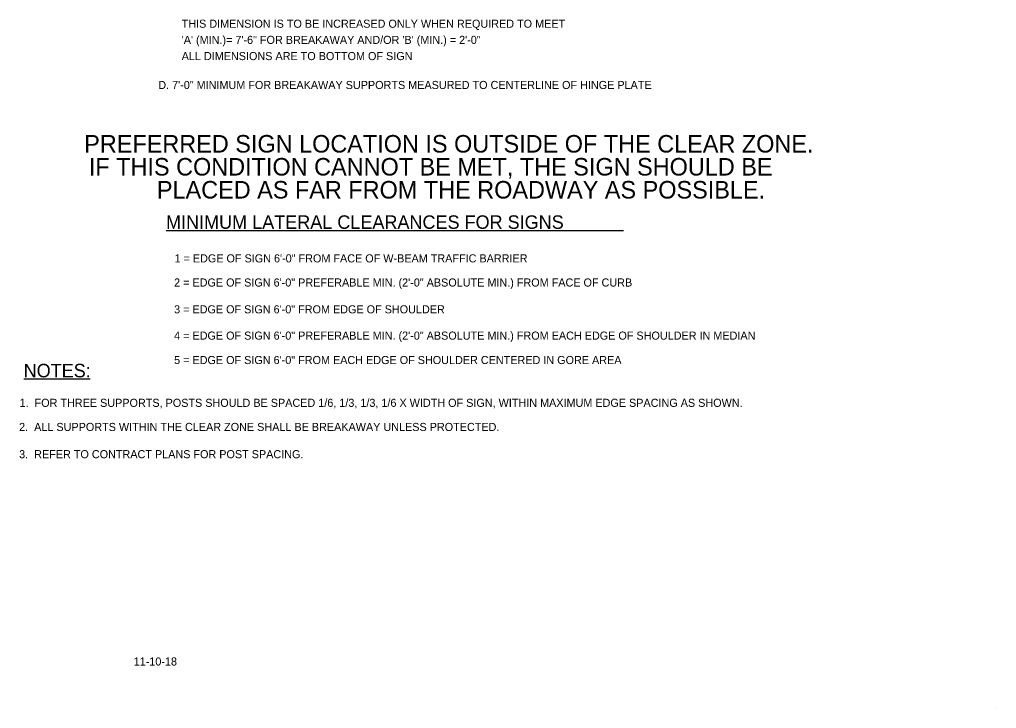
# Model space of a CAD drawing. Extents: x 139.2 to 146.5, y 202.4 to 212.6.
# Drawn here: x 139.25 to 146.5, y 202.38 to 207.49 of the extents above; entities that cross this region are included whole.
import ezdxf

# ---------------------------------------------------------------- set-up
doc = ezdxf.new("R2010")
doc.units = 0
for name, color, linetype in [('DETL-LINE', 7, 'Continuous'), ('DETL-NOTE', 7, 'Continuous'), ('TTLB-TEXT', 7, 'Continuous')]:
    doc.layers.add(name, color=color, linetype=linetype)

msp = doc.modelspace()

# ---------------------------------------------------------------- linework, layer by layer
at = {"layer": 'DETL-LINE'}
msp.add_line((140.3404, 205.922), (143.7331, 205.922), dxfattribs=at)
at = {"layer": 'DETL-NOTE'}
msp.add_line((139.2842, 204.8205), (139.7782, 204.8205), dxfattribs=at)
at = {"layer": 'TTLB-TEXT'}
msp.add_line((146.4995, 202.3768), (146.4995, 202.3768), dxfattribs=at)

# ---------------------------------------------------------------- texts
at = {"layer": 'DETL-LINE'}
msp.add_text('MINIMUM LATERAL CLEARANCES FOR SIGNS', height=0.100002, dxfattribs=at).set_placement((140.34, 205.9342))
at = {"layer": 'DETL-NOTE'}
for s, height, p in [('THIS DIMENSION IS TO BE INCREASED ONLY WHEN REQUIRED TO MEET ', 0.06, (140.4561, 207.4257)), ('\'A\' (MIN.)= 7\'-6" FOR BREAKAWAY AND/OR \'B\' (MIN.) = 2\'-0" ', 0.06, (140.4561, 207.3057)), ('ALL DIMENSIONS ARE TO BOTTOM OF SIGN', 0.06, (140.4561, 207.1857)), ('D. 7\'-0" MINIMUM FOR BREAKAWAY SUPPORTS MEASURED TO CENTERLINE OF HINGE PLATE', 0.06, (140.2826, 206.9712)), ('PREFERRED SIGN LOCATION IS OUTSIDE OF THE CLEAR ZONE.', 0.13, (139.7333, 206.5)), ('IF THIS CONDITION CANNOT BE MET, THE SIGN SHOULD BE ', 0.13, (139.7678, 206.3296)), ('PLACED AS FAR FROM THE ROADWAY AS POSSIBLE.', 0.13, (140.2722, 206.1591)), ('1 = EDGE OF SIGN 6\'-0" FROM FACE OF W-BEAM TRAFFIC BARRIER', 0.06, (140.403, 205.6852)), ('2 = EDGE OF SIGN 6\'-0" PREFERABLE MIN. (2\'-0" ABSOLUTE MIN.) FROM FACE OF CURB', 0.06, (140.4, 205.5062)), ('3 = EDGE OF SIGN 6\'-0" FROM EDGE OF SHOULDER', 0.06, (140.4, 205.3072)), ('4 = EDGE OF SIGN 6\'-0" PREFERABLE MIN. (2\'-0" ABSOLUTE MIN.) FROM EACH EDGE OF SHOULDER IN MEDIAN', 0.06, (140.4, 205.1122)), ('5 = EDGE OF SIGN 6\'-0" FROM EACH EDGE OF SHOULDER CENTERED IN GORE AREA', 0.06, (140.4, 204.9312)), ('NOTES:', 0.1, (139.2838, 204.8328)), ('1.  FOR THREE SUPPORTS, POSTS SHOULD BE SPACED 1/6, 1/3, 1/3, 1/6 X WIDTH OF SIGN, WITHIN MAXIMUM EDGE SPACING AS SHOWN.', 0.06, (139.2535, 204.6138)), ('2.  ALL SUPPORTS WITHIN THE CLEAR ZONE SHALL BE BREAKAWAY UNLESS PROTECTED.', 0.06, (139.2505, 204.4348)), ('3.  REFER TO CONTRACT PLANS FOR POST SPACING.', 0.06, (139.2505, 204.2328))]:
    msp.add_text(s, height=height, dxfattribs=at).set_placement(p)
at = {"layer": 'TTLB-TEXT'}
msp.add_text('11-10-18', height=0.06, dxfattribs=at).set_placement((140.1002, 202.6953))

doc.saveas('drawing.dxf')
